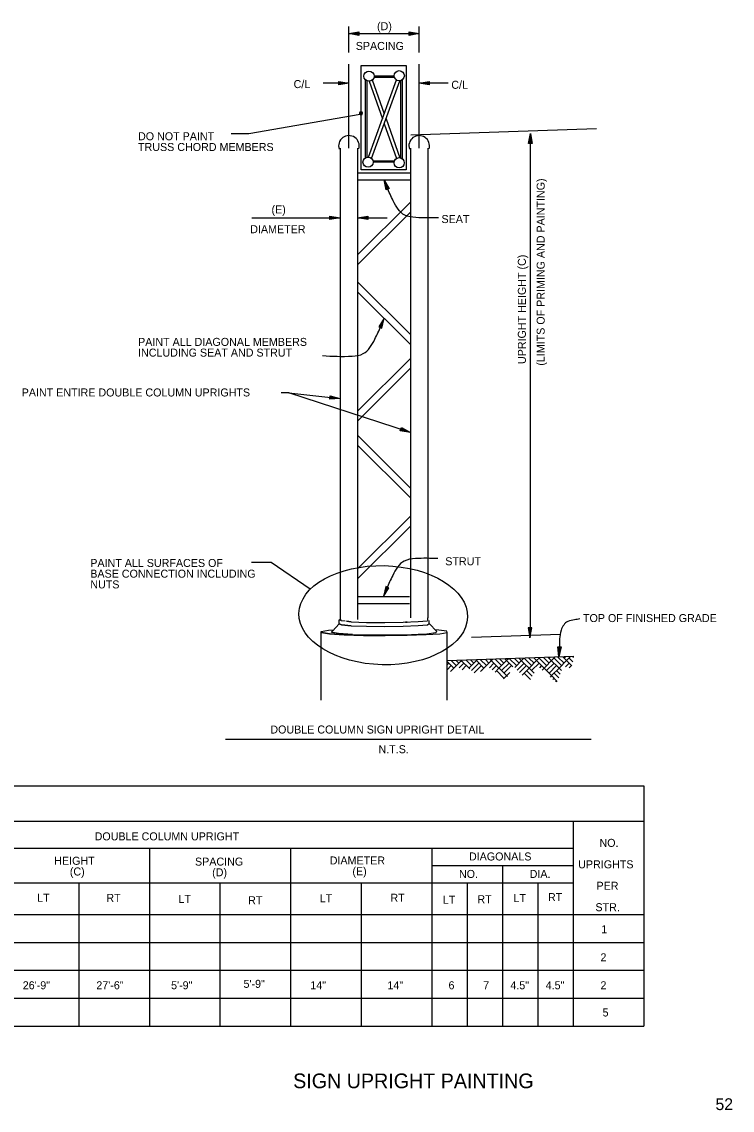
# Model space of a CAD drawing. Extents: x 10268852 to 10269008, y 2142584 to 2142686.
# Drawn here: x 10268947.8 to 10269008.1, y 2142586.4 to 2142678.9 of the extents above; entities that cross this region are included whole.
import ezdxf

# ---------------------------------------------------------------- set-up
doc = ezdxf.new("R2010")
doc.units = 0
for name, color, linetype in [('SignDetail', 7, 'Continuous'), ('TextDetails', 7, 'Continuous'), ('TextLabel', 7, 'Continuous'), ('TextMisc', 7, 'Continuous'), ('TextShtNo', 7, 'Continuous'), ('TextTables', 7, 'Continuous')]:
    doc.layers.add(name, color=color, linetype=linetype)

msp = doc.modelspace()

# ---------------------------------------------------------------- linework, layer by layer
at = {"layer": 'SignDetail'}
for p, q in [((10268976.947, 2142667.345), (10268976.947, 2142673.991)), ((10268977.096, 2142667.402), (10268977.096, 2142673.895)), ((10268977.212, 2142667.407), (10268979.593, 2142673.968)), ((10268977.264, 2142673.866), (10268978.395, 2142670.668)), ((10268977.474, 2142667.287), (10268979.869, 2142673.887)), ((10268977.534, 2142673.965), (10268978.55, 2142671.094)), ((10268977.678, 2142674.208), (10268979.414, 2142674.208)), ((10268977.687, 2142674.304), (10268979.397, 2142674.304)), ((10268979.946, 2142667.35), (10268979.946, 2142673.914)), ((10268980.094, 2142667.262), (10268980.094, 2142673.989)), ((10268978.546, 2142670.241), (10268979.588, 2142667.296)), ((10268978.701, 2142670.668), (10268979.872, 2142667.357)), ((10268977.59, 2142667.092), (10268979.417, 2142667.092)), ((10268977.605, 2142666.997), (10268979.39, 2142666.997)), ((10268976.29, 2142666.083), (10268980.771, 2142666.083)), ((10268976.29, 2142665.488), (10268980.771, 2142665.488)), ((10268976.29, 2142659.1), (10268980.771, 2142663.582)), ((10268976.29, 2142658.258), (10268980.771, 2142662.74)), ((10268976.289, 2142662.251), (10268978.804, 2142662.251)), ((10268976.29, 2142656.8), (10268980.771, 2142652.318)), ((10268976.29, 2142655.957), (10268980.771, 2142651.475)), ((10268976.29, 2142645.818), (10268980.771, 2142650.3)), ((10268976.29, 2142644.976), (10268980.771, 2142649.458)), ((10268976.29, 2142643.765), (10268980.771, 2142639.283)), ((10268976.29, 2142642.922), (10268980.771, 2142638.441)), ((10268976.29, 2142632.406), (10268980.771, 2142636.888)), ((10268976.29, 2142631.564), (10268980.771, 2142636.046)), ((10268976.29, 2142630.061), (10268980.693, 2142630.061)), ((10268976.29, 2142629.465), (10268980.693, 2142629.465)), ((10268994.654, 2142624.959), (10268983.899, 2142624.593)), ((10268992.338, 2142624.186), (10268991.701, 2142624.823)), ((10268992.975, 2142624.823), (10268993.614, 2142624.184)), ((10268984.459, 2142623.974), (10268983.899, 2142624.533)), ((10268986.386, 2142624.61), (10268985.747, 2142623.971)), ((10268987.023, 2142623.973), (10268986.386, 2142624.61)), ((10268988.724, 2142623.124), (10268988.087, 2142623.76)), ((10268988.937, 2142624.61), (10268988.298, 2142623.971)), ((10268989.15, 2142624.397), (10268988.511, 2142623.758)), ((10268989.363, 2142624.184), (10268988.724, 2142623.545)), ((10268991.488, 2142624.61), (10268990.85, 2142623.971)), ((10268991.701, 2142624.397), (10268991.063, 2142623.758)), ((10268992.125, 2142623.973), (10268991.488, 2142624.61)), ((10268992.125, 2142623.973), (10268992.764, 2142623.334)), ((10268992.975, 2142624.397), (10268992.338, 2142623.76)), ((10268993.188, 2142624.184), (10268992.551, 2142623.547)), ((10268993.401, 2142623.971), (10268992.764, 2142623.334)), ((10268994.04, 2142624.61), (10268993.401, 2142623.971))]:
    msp.add_line(p, q, dxfattribs=at)
msp.add_lwpolyline([(10268980.402, 2142666.324), (10268976.576, 2142666.324), (10268976.576, 2142675.204), (10268980.402, 2142675.204)], close=True, dxfattribs=at)
for points in [[(10268974.8, 2142668.183), (10268974.8, 2142628.099)], [(10268976.289, 2142668.183), (10268976.289, 2142628.099)], [(10268980.771, 2142668.183), (10268980.771, 2142628.236)], [(10268982.26, 2142668.183), (10268982.26, 2142628.236)], [(10268975.859, 2142626.845), (10268974.673, 2142626.918), (10268974.076, 2142627.012), (10268974.16, 2142627.112), (10268974.719, 2142627.746), (10268974.914, 2142627.656), (10268975.737, 2142627.579)], [(10268975.232, 2142627.964), (10268974.914, 2142627.994), (10268974.719, 2142628.084), (10268974.882, 2142628.114)], [(10268975.737, 2142627.579), (10268974.914, 2142627.656), (10268974.719, 2142627.746), (10268974.719, 2142628.084)], [(10268974.914, 2142627.656), (10268974.719, 2142627.746)], [(10268974.914, 2142627.656), (10268974.719, 2142627.746)], [(10268974.719, 2142627.746), (10268974.914, 2142627.656), (10268975.737, 2142627.579), (10268977.045, 2142627.527), (10268978.613, 2142627.51)], [(10268974.914, 2142627.656), (10268975.737, 2142627.579)], [(10268974.914, 2142627.656), (10268975.737, 2142627.579)], [(10268975.737, 2142627.917), (10268975.347, 2142627.954)], [(10268975.347, 2142627.954), (10268975.737, 2142627.917), (10268977.045, 2142627.865), (10268978.613, 2142627.848)], [(10268975.737, 2142627.917), (10268977.045, 2142627.865), (10268978.613, 2142627.848), (10268980.169, 2142627.868)], [(10268975.737, 2142627.579), (10268977.045, 2142627.527), (10268978.613, 2142627.51)], [(10268975.737, 2142627.579), (10268977.046, 2142627.527)], [(10268975.737, 2142627.579), (10268977.045, 2142627.527), (10268978.613, 2142627.51), (10268980.169, 2142627.53)], [(10268975.737, 2142627.579), (10268977.046, 2142627.527)], [(10268977.045, 2142627.527), (10268978.613, 2142627.51)], [(10268977.045, 2142627.527), (10268978.613, 2142627.51)], [(10268977.673, 2142627.859), (10268977.678, 2142627.859)], [(10268978.613, 2142627.848), (10268980.169, 2142627.868), (10268981.443, 2142627.923)], [(10268978.613, 2142627.51), (10268980.169, 2142627.53), (10268981.443, 2142627.584)], [(10268978.613, 2142627.51), (10268980.169, 2142627.53)], [(10268978.613, 2142627.51), (10268980.169, 2142627.53)], [(10268978.613, 2142627.51), (10268980.169, 2142627.53)], [(10268980.169, 2142627.868), (10268981.443, 2142627.923)], [(10268980.169, 2142627.53), (10268981.444, 2142627.585)], [(10268980.169, 2142627.53), (10268981.444, 2142627.585)], [(10268980.169, 2142627.53), (10268981.443, 2142627.584)], [(10268980.169, 2142627.53), (10268981.443, 2142627.584)], [(10268980.487, 2142627.882), (10268980.369, 2142627.889), (10268980.487, 2142627.882)], [(10268980.487, 2142627.882), (10268980.369, 2142627.889), (10268980.487, 2142627.882)], [(10268981.443, 2142627.923), (10268982.217, 2142628.001)], [(10268981.443, 2142627.923), (10268982.217, 2142628.001)], [(10268981.443, 2142627.584), (10268982.217, 2142627.663), (10268982.356, 2142627.753)], [(10268981.443, 2142627.584), (10268982.217, 2142627.663), (10268982.356, 2142627.753), (10268983.01, 2142627.09)], [(10268981.443, 2142627.584), (10268982.217, 2142627.663)], [(10268981.444, 2142627.584), (10268982.217, 2142627.663)], [(10268981.444, 2142627.584), (10268982.217, 2142627.663)], [(10268982.217, 2142627.663), (10268982.356, 2142627.753), (10268982.356, 2142628.009)], [(10268982.217, 2142627.663), (10268982.356, 2142627.753)], [(10268982.217, 2142627.663), (10268982.356, 2142627.753)], [(10268982.26, 2142628.01), (10268982.26, 2142628.236)], [(10268978.642, 2142626.744), (10268976.782, 2142626.76), (10268975.135, 2142626.812), (10268973.899, 2142626.892), (10268973.223, 2142626.991), (10268973.189, 2142627.098), (10268973.801, 2142627.199), (10268974.265, 2142627.231)], [(10268973.189, 2142627.098), (10268973.802, 2142627.199)], [(10268973.189, 2142627.098), (10268973.223, 2142626.991), (10268973.899, 2142626.892), (10268975.135, 2142626.812), (10268976.782, 2142626.76), (10268978.642, 2142626.744)], [(10268973.19, 2142621.248), (10268973.19, 2142627.098), (10268973.801, 2142627.199), (10268974.265, 2142627.231)], [(10268973.801, 2142627.199), (10268974.265, 2142627.231)], [(10268974.673, 2142626.919), (10268974.144, 2142627.002)], [(10268974.673, 2142626.919), (10268974.144, 2142627.002)], [(10268974.673, 2142626.919), (10268974.786, 2142626.911)], [(10268974.673, 2142626.919), (10268974.786, 2142626.911)], [(10268975.859, 2142626.845), (10268977.453, 2142626.802)], [(10268977.453, 2142626.802), (10268979.214, 2142626.798)], [(10268977.628, 2142626.802), (10268979.214, 2142626.798)], [(10268977.628, 2142626.802), (10268979.214, 2142626.798)], [(10268978.642, 2142626.744), (10268980.489, 2142626.764), (10268982.103, 2142626.819), (10268983.287, 2142626.902), (10268983.899, 2142627.002), (10268983.865, 2142627.109), (10268983.189, 2142627.208), (10268982.873, 2142627.229)], [(10268978.642, 2142626.744), (10268980.489, 2142626.764), (10268982.103, 2142626.819)], [(10268979.214, 2142626.798), (10268980.873, 2142626.832)], [(10268979.214, 2142626.798), (10268979.493, 2142626.803)], [(10268979.214, 2142626.798), (10268979.493, 2142626.803)], [(10268980.873, 2142626.832), (10268982.177, 2142626.899), (10268982.929, 2142626.988), (10268983.012, 2142627.088)], [(10268981.426, 2142626.86), (10268982.177, 2142626.899), (10268982.929, 2142626.988)], [(10268981.426, 2142626.86), (10268982.177, 2142626.899), (10268982.929, 2142626.988)], [(10268982.103, 2142626.819), (10268983.287, 2142626.902), (10268983.899, 2142627.002), (10268983.865, 2142627.109), (10268983.189, 2142627.208), (10268982.873, 2142627.229)], [(10268983.899, 2142627.002), (10268983.865, 2142627.109), (10268983.19, 2142627.208), (10268982.873, 2142627.229)], [(10268982.929, 2142626.988), (10268982.951, 2142627.015)], [(10268982.929, 2142626.988), (10268982.951, 2142627.015)], [(10268983.899, 2142621.248), (10268983.899, 2142627.002)], [(10268985.908, 2142624.661), (10268986.173, 2142624.397)], [(10268986.32, 2142624.675), (10268986.386, 2142624.61)], [(10268986.456, 2142624.68), (10268986.386, 2142624.61)], [(10268986.732, 2142623.682), (10268987.774, 2142624.725)], [(10268987.235, 2142624.186), (10268986.732, 2142624.69)], [(10268987.449, 2142624.399), (10268987.144, 2142624.703)], [(10268989.014, 2142623.256), (10268987.552, 2142624.717)], [(10268987.964, 2142624.731), (10268988.511, 2142624.184)], [(10268988.376, 2142624.745), (10268988.724, 2142624.397)], [(10268988.788, 2142624.759), (10268988.937, 2142624.61)], [(10268989.097, 2142624.769), (10268988.937, 2142624.61)], [(10268989.787, 2142624.186), (10268989.2, 2142624.773)], [(10268990, 2142624.399), (10268989.612, 2142624.787)], [(10268989.633, 2142624.032), (10268990.415, 2142624.815)], [(10268991.274, 2142623.547), (10268990.019, 2142624.801)], [(10268990.431, 2142624.815), (10268991.063, 2142624.184)], [(10268990.843, 2142624.829), (10268991.276, 2142624.397)], [(10268991.255, 2142624.843), (10268991.488, 2142624.61)], [(10268991.297, 2142624.845), (10268991.276, 2142624.823)], [(10268991.738, 2142624.859), (10268991.488, 2142624.61)], [(10268991.954, 2142623.802), (10268993.057, 2142624.904)], [(10268992.551, 2142624.399), (10268992.079, 2142624.871)], [(10268993.597, 2142623.775), (10268992.487, 2142624.885)], [(10268992.62, 2142624.89), (10268992.551, 2142624.821)], [(10268993.311, 2142624.913), (10268993.827, 2142624.397)], [(10268993.723, 2142624.927), (10268994.04, 2142624.61)], [(10268993.938, 2142624.934), (10268993.827, 2142624.823)], [(10268994.379, 2142624.949), (10268994.04, 2142624.61)], [(10268994.566, 2142624.51), (10268994.253, 2142624.823)], [(10268994.636, 2142624.866), (10268994.547, 2142624.955)], [(10268984.035, 2142624.397), (10268983.899, 2142624.261)], [(10268984.248, 2142624.184), (10268983.899, 2142623.836)], [(10268984.167, 2142623.682), (10268985.12, 2142624.635)], [(10268984.245, 2142623.76), (10268984.253, 2142623.753)], [(10268984.671, 2142624.186), (10268984.252, 2142624.606)], [(10268984.458, 2142623.973), (10268984.485, 2142623.947)], [(10268984.884, 2142624.399), (10268984.664, 2142624.62)], [(10268985.308, 2142624.397), (10268984.919, 2142624.008)], [(10268985.059, 2142624.561), (10268985.134, 2142624.635)], [(10268985.817, 2142623.901), (10268985.084, 2142624.634)], [(10268985.521, 2142624.184), (10268985.158, 2142623.821)], [(10268985.321, 2142624.397), (10268985.287, 2142624.363)], [(10268985.497, 2142624.647), (10268985.96, 2142624.184)], [(10268985.534, 2142624.184), (10268985.515, 2142624.165)], [(10268985.747, 2142623.971), (10268985.742, 2142623.966)], [(10268986.599, 2142624.397), (10268985.97, 2142623.768)], [(10268986.812, 2142624.184), (10268986.198, 2142623.57)], [(10268986.81, 2142623.76), (10268986.817, 2142623.753)], [(10268987.023, 2142623.973), (10268987.049, 2142623.947)], [(10268987.872, 2142624.397), (10268987.483, 2142624.008)], [(10268988.085, 2142624.184), (10268987.722, 2142623.821)], [(10268988.298, 2142623.971), (10268987.961, 2142623.634)], [(10268989.474, 2142624.073), (10268988.937, 2142624.61)], [(10268990.424, 2142624.397), (10268989.84, 2142623.813)], [(10268990.637, 2142624.184), (10268990.047, 2142623.594)], [(10268990.85, 2142623.971), (10268990.254, 2142623.376)], [(10268991.123, 2142623.276), (10268990.639, 2142623.76)], [(10268991.914, 2142624.184), (10268991.727, 2142623.997)], [(10268993.483, 2142623.467), (10268993.19, 2142623.76)], [(10268994.253, 2142624.397), (10268993.943, 2142624.087)], [(10268994.496, 2142624.154), (10268994.04, 2142624.61)], [(10268994.466, 2142624.184), (10268994.267, 2142623.986)], [(10268988.676, 2142623.076), (10268989.216, 2142623.615)], [(10268989.148, 2142623.547), (10268989.167, 2142623.528)], [(10268990.971, 2142623.002), (10268990.426, 2142623.547)], [(10268992.764, 2142623.334), (10268992.641, 2142623.211)], [(10268993.254, 2142622.844), (10268992.764, 2142623.334)], [(10268992.977, 2142623.121), (10268992.87, 2142623.014)], [(10268993.369, 2142623.155), (10268992.977, 2142623.547)], [(10268993.19, 2142622.909), (10268993.098, 2142622.817)]]:
    msp.add_lwpolyline(points, dxfattribs=at)
for centre in [(10268977.255, 2142674.295), (10268979.829, 2142674.33), (10268977.173, 2142666.976), (10268979.817, 2142666.93)]:
    msp.add_circle(centre, 0.432, dxfattribs=at)
for centre, radius, start, end in [((10268976.572, 2142671.129), 0.133, 233.1476, 214.08238), ((10268975.548, 2142668.363), 0.876, 343.69915, 198.54837), ((10268981.519, 2142668.363), 0.876, 343.69915, 198.54837)]:
    msp.add_arc(centre, radius, start, end, dxfattribs=at)
at = {"layer": 'TextDetails'}
msp.add_line((10268965.077, 2142617.945), (10268996.143, 2142617.945), dxfattribs=at)
at = {"layer": 'TextLabel'}
for p, q in [((10268975.545, 2142676.308), (10268975.545, 2142678.512)), ((10268981.516, 2142676.308), (10268981.516, 2142678.512)), ((10268975.545, 2142677.904), (10268981.516, 2142677.904)), ((10268975.545, 2142668.183), (10268975.545, 2142675.32)), ((10268981.516, 2142668.183), (10268981.516, 2142675.32)), ((10268975.545, 2142673.696), (10268973.373, 2142673.696)), ((10268983.97, 2142673.696), (10268981.516, 2142673.696)), ((10268976.492, 2142671.023), (10268967.033, 2142669.376)), ((10268967.033, 2142669.376), (10268965.556, 2142669.376)), ((10268996.59, 2142669.813), (10268980.819, 2142669.276)), ((10268990.962, 2142626.653), (10268990.962, 2142669.169)), ((10268967.298, 2142662.251), (10268974.8, 2142662.251)), ((10268970.437, 2142647.373), (10268969.805, 2142647.373)), ((10268980.771, 2142644.01), (10268970.437, 2142647.373)), ((10268970.437, 2142647.373), (10268974.787, 2142646.891)), ((10268968.956, 2142632.939), (10268967.282, 2142632.939)), ((10268972.269, 2142630.677), (10268968.956, 2142632.939)), ((10268993.521, 2142626.831), (10268985.952, 2142626.574))]:
    msp.add_line(p, q, dxfattribs=at)
for points in [[(10268975.545, 2142677.904), (10268976.403, 2142678.048), (10268976.403, 2142677.76)], [(10268975.799, 2142677.904), (10268976.375, 2142677.993), (10268976.375, 2142677.815)], [(10268976.032, 2142677.904), (10268976.327, 2142677.952), (10268976.327, 2142677.856)], [(10268981.516, 2142677.904), (10268980.658, 2142677.76), (10268980.658, 2142678.048)], [(10268981.262, 2142677.904), (10268980.685, 2142677.814), (10268980.685, 2142677.993)], [(10268981.029, 2142677.904), (10268980.733, 2142677.856), (10268980.733, 2142677.952)], [(10268975.545, 2142673.696), (10268974.687, 2142673.552), (10268974.687, 2142673.84)], [(10268975.291, 2142673.696), (10268974.714, 2142673.607), (10268974.714, 2142673.785)], [(10268975.058, 2142673.696), (10268974.762, 2142673.648), (10268974.762, 2142673.744)], [(10268981.516, 2142673.696), (10268982.374, 2142673.84), (10268982.374, 2142673.552)], [(10268981.77, 2142673.696), (10268982.346, 2142673.785), (10268982.346, 2142673.607)], [(10268982.003, 2142673.696), (10268982.298, 2142673.744), (10268982.298, 2142673.648)], [(10268990.962, 2142669.419), (10268991.106, 2142668.561), (10268990.818, 2142668.561)], [(10268990.962, 2142669.165), (10268991.052, 2142668.588), (10268990.873, 2142668.588)], [(10268990.962, 2142668.931), (10268991.01, 2142668.636), (10268990.914, 2142668.636)], [(10268978.531, 2142665.488), (10268978.982, 2142664.744), (10268978.714, 2142664.638)], [(10268978.624, 2142665.252), (10268978.921, 2142664.75), (10268978.755, 2142664.683)], [(10268978.711, 2142665.035), (10268978.865, 2142664.779), (10268978.775, 2142664.743)], [(10268974.8, 2142662.251), (10268973.942, 2142662.107), (10268973.942, 2142662.395)], [(10268974.546, 2142662.251), (10268973.97, 2142662.162), (10268973.97, 2142662.34)], [(10268974.313, 2142662.251), (10268974.018, 2142662.203), (10268974.018, 2142662.299)], [(10268976.289, 2142662.251), (10268977.147, 2142662.395), (10268977.147, 2142662.107)], [(10268976.543, 2142662.251), (10268977.12, 2142662.341), (10268977.12, 2142662.162)], [(10268976.777, 2142662.251), (10268977.072, 2142662.3), (10268977.072, 2142662.203)], [(10268978.531, 2142653.716), (10268978.079, 2142652.973), (10268978.347, 2142652.866)], [(10268978.437, 2142653.48), (10268978.14, 2142652.978), (10268978.306, 2142652.912)], [(10268978.35, 2142653.264), (10268978.196, 2142653.007), (10268978.286, 2142652.972)], [(10268974.787, 2142646.891), (10268973.919, 2142646.83), (10268973.947, 2142647.117)], [(10268974.534, 2142646.915), (10268973.951, 2142646.882), (10268973.969, 2142647.06)], [(10268974.302, 2142646.938), (10268974.003, 2142646.919), (10268974.012, 2142647.014)], [(10268980.771, 2142644.009), (10268979.913, 2142644.152), (10268980.007, 2142644.425)], [(10268980.531, 2142644.092), (10268979.957, 2142644.195), (10268980.015, 2142644.364)], [(10268980.31, 2142644.168), (10268980.016, 2142644.218), (10268980.047, 2142644.309)], [(10268978.491, 2142630.061), (10268978.943, 2142630.804), (10268978.675, 2142630.911)], [(10268978.585, 2142630.297), (10268978.881, 2142630.799), (10268978.716, 2142630.865)], [(10268978.671, 2142630.513), (10268978.825, 2142630.77), (10268978.736, 2142630.805)], [(10268990.932, 2142626.554), (10268991.076, 2142627.412), (10268990.788, 2142627.412)], [(10268990.932, 2142626.808), (10268991.021, 2142627.385), (10268990.843, 2142627.385)], [(10268990.932, 2142627.041), (10268990.98, 2142627.337), (10268990.884, 2142627.337)], [(10268993.38, 2142624.922), (10268993.29, 2142625.787), (10268993.578, 2142625.769)], [(10268993.396, 2142625.175), (10268993.343, 2142625.756), (10268993.521, 2142625.745)], [(10268993.411, 2142625.408), (10268993.381, 2142625.705), (10268993.477, 2142625.699)]]:
    msp.add_lwpolyline(points, close=True, dxfattribs=at)
msp.add_ellipse((10268978.464, 2142628.471), major_axis=(7.162, -0.159), ratio=0.588001, dxfattribs=at)
for points in [[(10268983.151, 2142662.259), (10268981.239, 2142662.269), (10268980.292, 2142662.474), (10268979.31, 2142663.694), (10268978.8, 2142664.811), (10268978.531, 2142665.488)], [(10268973.309, 2142650.538), (10268975.822, 2142650.498), (10268976.769, 2142650.703), (10268977.751, 2142651.923), (10268978.261, 2142653.039), (10268978.531, 2142653.716)], [(10268983.111, 2142633.289), (10268981.199, 2142633.279), (10268980.253, 2142633.074), (10268979.27, 2142631.854), (10268978.761, 2142630.738), (10268978.491, 2142630.061)], [(10268995.154, 2142628.172), (10268994.709, 2142628.072), (10268994.144, 2142627.95), (10268993.577, 2142627.188), (10268993.43, 2142625.711), (10268993.38, 2142624.922)]]:
    msp.add_spline(points, degree=3, dxfattribs=at)
at = {"layer": 'TextTables'}
for p, q in [((10268900.595, 2142613.976), (10269000.595, 2142613.976)), ((10269000.595, 2142613.976), (10269000.595, 2142593.534)), ((10268900.595, 2142610.976), (10269000.595, 2142610.976)), ((10268994.595, 2142610.976), (10268994.595, 2142593.534)), ((10268922.595, 2142608.66), (10268994.595, 2142608.66)), ((10268958.595, 2142608.66), (10268958.595, 2142593.534)), ((10268970.595, 2142608.66), (10268970.595, 2142593.534)), ((10268982.595, 2142608.66), (10268982.595, 2142593.534)), ((10268982.595, 2142607.193), (10268994.595, 2142607.193)), ((10268988.595, 2142607.193), (10268988.595, 2142593.534)), ((10268922.595, 2142605.725), (10268994.595, 2142605.725)), ((10268952.595, 2142605.725), (10268952.595, 2142593.534)), ((10268964.595, 2142605.725), (10268964.595, 2142593.534)), ((10268976.595, 2142605.725), (10268976.595, 2142593.534)), ((10268985.595, 2142605.725), (10268985.595, 2142593.534)), ((10268991.595, 2142605.725), (10268991.595, 2142593.534)), ((10268900.595, 2142603.042), (10269000.595, 2142603.042)), ((10268900.595, 2142600.665), (10269000.595, 2142600.665)), ((10268900.595, 2142598.288), (10269000.595, 2142598.288)), ((10268900.595, 2142595.911), (10269000.595, 2142595.911)), ((10268900.595, 2142593.534), (10269000.595, 2142593.534))]:
    msp.add_line(p, q, dxfattribs=at)

# ---------------------------------------------------------------- texts
at = {"layer": 'SignDetail'}
msp.add_text('5', height=0.68, dxfattribs=at).set_placement((10268997.1, 2142594.366))
at = {"layer": 'TextDetails'}
for s, p in [('DOUBLE COLUMN SIGN UPRIGHT DETAIL', (10268968.873, 2142618.416)), ('N.T.S.', (10268978.061, 2142616.741))]:
    msp.add_text(s, height=0.68, dxfattribs=at).set_placement(p)
at = {"layer": 'TextLabel'}
for s, p in [('(D)', (10268977.939, 2142678.197)), ('SPACING', (10268976.13, 2142676.519)), ('C/L', (10268970.849, 2142673.276)), ('C/L', (10268984.247, 2142673.215)), ('DO NOT PAINT ', (10268957.634, 2142668.841)), ('TRUSS CHORD MEMBERS', (10268957.634, 2142667.929)), ('(E)', (10268968.973, 2142662.62)), ('SEAT', (10268983.415, 2142661.803)), ('DIAMETER', (10268967.164, 2142660.943)), ('PAINT ALL DIAGONAL MEMBERS', (10268957.638, 2142651.363)), ('INCLUDING SEAT AND STRUT', (10268957.638, 2142650.452)), ('PAINT ENTIRE DOUBLE COLUMN UPRIGHTS', (10268947.751, 2142647.065)), ('PAINT ALL SURFACES OF ', (10268953.578, 2142632.572)), ('STRUT', (10268983.735, 2142632.716)), ('BASE CONNECTION INCLUDING ', (10268953.578, 2142631.661)), ('NUTS', (10268953.578, 2142630.749)), ('TOP OF FINISHED GRADE', (10268995.435, 2142627.888))]:
    msp.add_text(s, height=0.68, dxfattribs=at).set_placement(p)
for s, p in [('(LIMITS OF PRIMING AND PAINTING)', (10268992.18, 2142649.681)), ('UPRIGHT HEIGHT (C)', (10268990.582, 2142649.822))]:
    msp.add_text(s, height=0.68, rotation=90, dxfattribs=at).set_placement(p)
at = {"layer": 'TextMisc'}
msp.add_text('    SIGN UPRIGHT PAINTING      ', height=1.25, rotation=360, dxfattribs=at).set_placement((10268968.954, 2142588.266))
at = {"layer": 'TextShtNo'}
msp.add_text('52', height=1, rotation=360, dxfattribs=at).set_placement((10269006.693, 2142586.409))
at = {"layer": 'TextTables'}
for s, p in [('DOUBLE COLUMN UPRIGHT', (10268953.947, 2142609.334)), ('NO.', (10268996.835, 2142608.779)), ('DIAGONALS', (10268985.749, 2142607.625)), ('HEIGHT', (10268950.518, 2142607.258)), ('SPACING', (10268962.474, 2142607.189)), ('DIAMETER', (10268973.92, 2142607.284)), ('(E)', (10268975.846, 2142606.373)), ('UPRIGHTS', (10268995.026, 2142606.957)), ('(C)', (10268951.84, 2142606.347)), ('(D)', (10268963.931, 2142606.277)), ('NO.', (10268984.9, 2142606.14)), ('DIA.', (10268990.906, 2142606.14)), ('PER', (10268996.582, 2142605.134)), ('LT', (10268949.068, 2142604.116)), ('RT', (10268954.941, 2142604.104)), ('LT', (10268961.068, 2142604.015)), ('RT', (10268966.991, 2142603.903)), ('LT', (10268973.068, 2142604.079)), ('RT', (10268979.078, 2142604.116)), ('LT', (10268983.53, 2142603.944)), ('RT', (10268986.461, 2142603.994)), ('LT', (10268989.53, 2142604.081)), ('RT', (10268992.461, 2142604.17)), ('STR.', (10268996.494, 2142603.312)), ('1', (10268996.983, 2142601.431)), ('2', (10268996.922, 2142599.054)), ('26\'-9"', (10268947.84, 2142596.677)), ('27\'-6"', (10268954.091, 2142596.677)), ('5\'-9"', (10268960.443, 2142596.677)), ('5\'-9"', (10268966.595, 2142596.798)), ('14"', (10268972.271, 2142596.677)), ('14"', (10268978.823, 2142596.677)), ('6', (10268984.012, 2142596.677)), ('7', (10268986.957, 2142596.677)), ('4.5"', (10268989.267, 2142596.677)), ('4.5"', (10268992.268, 2142596.677)), ('2', (10268996.922, 2142596.677))]:
    msp.add_text(s, height=0.68, dxfattribs=at).set_placement(p)

doc.saveas('drawing.dxf')
